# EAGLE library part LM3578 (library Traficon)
Buck - Boost - Buckboost regulator Farnell 953-775
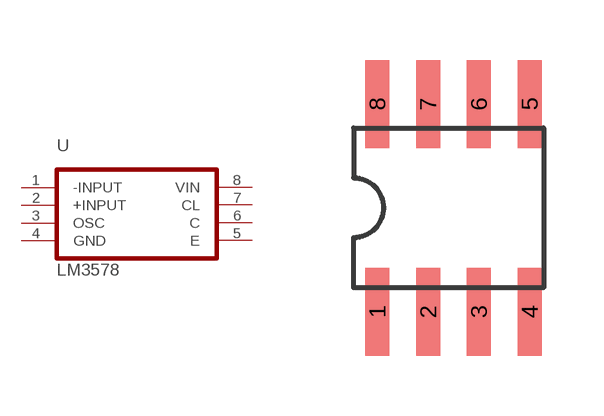
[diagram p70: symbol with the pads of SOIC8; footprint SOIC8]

Designator prefix U

## LM3578  [SOIC8]
1  -INPUT
2  +INPUT
3  OSC
4  GND
5  E
6  C
7  CL
8  VIN

## Footprint SOIC8 (pad centres in mm)
Small Outline IC
smd 0.6 x 2.2: 1 -1.905,-2.6; 2 -0.635,-2.6; 3 0.635,-2.6; 4 1.905,-2.6; 5 1.905,2.6; 6 0.635,2.6; 7 -0.635,2.6; 8 -1.905,2.6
